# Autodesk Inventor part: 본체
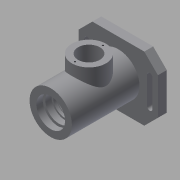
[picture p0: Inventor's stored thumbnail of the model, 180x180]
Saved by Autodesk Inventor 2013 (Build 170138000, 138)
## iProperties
Created: 2017-10
Part Number: 본체
Material: 일반
Document SubType Name: Modeling
Designer: Windows7
Density: 1 g/cm^3
Author: Windows7
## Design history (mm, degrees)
sketch "스케치1"
  geometry: L1 (58, -47)-(-58, -47); L2 (-58, -47)-(-58, 47); L3 (-58, 47)-(58, 47); L4 (58, 47)-(58, -47); L5 (58, -47)-(-58, 47); L6 (-58, -47)-(58, 47); L7 (-50, 20)-(-50, -20); L8 (-42, -20)-(-42, 20); L9 (0, 47)-(0, -47); L10 (-58, -47)-(58, 47); L11 (58, -47)-(-58, 47); L12 (50, 20)-(50, -20); L13 (42, -20)-(42, 20); A1 r 4 centre (-46, 20) between (-42, 20) and (-50, 20); A2 r 4 centre (-46, -20) between (-50, -20) and (-42, -20); A3 r 4 centre (46, 20) between (50, 20) and (42, 20); A4 r 4 centre (46, -20) between (42, -20) and (50, -20); 1 further point
  constraints: 26 end point, 10 symmetric about line, 8 point on circle, 4 centre point, 4 midpoint, 3 parallel, 2 tangent, 1 horizontal, 1 perpendicular, 2 other
  dimensions: "d0" = 116 distance of L2.end L3.end; "d1" = 94 distance of L1.end L2.end; "d5" = 8 diameter of A1; "d6" = 8 diameter of A2
extrude "돌출1" new body sketch "스케치1" distance "d7" = 13; taper "d8" = 0 deg
chamfer "모따기1" distance "d9" = 20; stored, may be unused: second distance "d10" = 2, angle "d11" = 45 deg
sketch "스케치2"
  geometry: C1 r 35 at (0, 0); 1 further point
  constraints: 1 centre point, 1 coincident
  dimensions: "d12" = 70 diameter of C1
extrude "돌출2" join sketch "스케치2" distance "d13" = 3; taper "d14" = 0 deg
extrude "돌출3" cut sketch "스케치1" distance "d15" = 13; taper "d16" = 0 deg
sketch "스케치3"
  geometry: C1 r 31 at (0, 0); 1 further point
  constraints: 1 centre point, 1 coincident
  dimensions: "d17" = 62 diameter of C1
extrude "돌출4" join sketch "스케치3" distance "d18" = 99; taper "d19" = 0 deg
sketch "스케치5"
  geometry: L1 (31, 112)-(-31, 112) reference; L2 (0, 112)-(56, 112); L3 (0, 112)-(0, 56); C1 r 25 at (0, 56); C2 r 16 at (0, 56); 1 further point
  constraints: 4 end point, 2 centre point, 2 coincident, 1 horizontal, 1 midpoint
  dimensions: "d22" = 50 diameter of C1; "d23" = 32 diameter of C2
extrude "돌출5" join sketch "스케치5" distance "d24" = 47; taper "d25" = 0 deg
sketch "스케치6"
  geometry: C1 r 25 at (0, 0) reference; C2 r 16 at (0, 0); 1 further point
  constraints: 1 centre point, 1 coincident
  dimensions: "d26" = 32 diameter of C2
extrude "돌출6" cut sketch "스케치6" distance "d27" = 47; taper "d28" = 0 deg
sketch "스케치7"
  geometry: L1 (112, -31)-(112, 31) reference; L2 (112, 0)-(112, -21); L3 (112, 0)-(-3, 0); L4 (0, -35)-(0, 35) reference; L5 (112, -21)-(103, -21); L6 (103, -21)-(103, -24); L7 (103, -24)-(100, -24); L8 (100, -24)-(100, -20); L9 (100, -20)-(91, -20); L10 (91, -17.5)-(87.75, -17.5); L11 (87.75, -18.5)-(86, -18.5); L12 (86, -17.5)-(75, -17.5); L13 (75, -26)-(37, -26); L14 (86, -18.5)-(86, -17.5); L15 (91, -20)-(91, -17.5); L16 (87.75, -18.5)-(87.75, -17.5); L17 (75, -26)-(75, -17.5); L18 (37, -17.5)-(26, -17.5); L19 (13, 31)-(13, -31) reference; L20 (37, -26)-(37, -17.5); L21 (26, -16.051)-(21, -16.051); L22 (26, -17.5)-(26, -16.051); L23 (21, -10)-(18.3, -10); L24 (18.3, -10)-(18.3, -12.5); L25 (18.3, -12.5)-(11, -12.5); L26 (-3, 35)-(-3, -35) reference; L27 (-3, 0)-(-3, -22); L28 (-3, -22)-(11, -16); L29 (11, -16)-(11, -12.5); L30 (21, -16.051)-(21, -10); 1 further point
  constraints: 52 end point, 7 parallel, 7 perpendicular, 2 midpoint, 2 point on line
  dimensions: "d29" = 21 distance of L2.start L2.end; "d30" = 9 distance of L2.end L5.end; "d31" = 3 distance of L5.end L6.end; "d32" = 3 distance of L6.end L7.end; "d33" = 4 distance of L7.end L8.end; "d34" = 9 distance of L8.end L9.end; "d36" = 3.25 distance of L10.start L10.end; "d38" = 1.75 distance of L11.start L11.end; "d40" = 11 distance of L12.start L12.end; "d42" = 38 distance of L13.start L13.end; "d44" = 11 distance of L18.start L18.end; "d46" = 5 distance of L21.start L21.end; "d48" = 2.7 distance of L23.start L23.end; "d49" = 2.5 distance of L23.end L24.end; "d50" = 7.3 distance of L24.end L25.end; "d52" = 22 distance of L3.end L27.end
revolve "회전1" sketch "스케치7" stored, may be unused: angle "d53" = 90 deg
sketch "스케치8"
  geometry: 2 further points
hole "구멍1" sketch "스케치8" at (0, 20.5) diameter "d55" = 2.459; stored, may be unused: countersink angle "d59" = 90 deg, drill point angle "d61" = 118 deg; dims "d56" = 6, "d57" = 4, "d58" = 2, "d60" = 8
node "작업 평면1"
node "솔리드1"
mirror "대칭1"
other parameters: "d62" = -56
